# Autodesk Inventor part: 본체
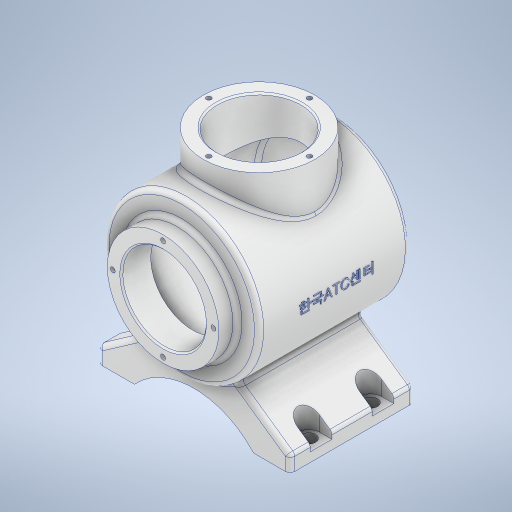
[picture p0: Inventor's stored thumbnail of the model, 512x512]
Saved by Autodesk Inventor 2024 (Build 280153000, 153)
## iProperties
Created: 2023-08
Part Number: 본체
Material: 알루미늄 6061
Document SubType Name: Modeling
Designer: Owner
Density: 2.7 g/cm^3
Appearance: 알루미늄 - 평지
Mass: 1315.98 g
Surface Area: 1059.75 cm^2
Volume: 487.401 cm^3
Author: Owner
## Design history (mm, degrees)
sketch "스케치1"
  geometry: L1 (0, 0)-(36, 0); L2 (36, 0)-(36, -12); L3 (36, -12)-(0, -12); L4 (0, -12)-(0, 0); L5 (0, -12)-(50, -12); L6 (50, -12)-(50, -120); L7 (50, -120)-(0, -120); L8 (0, -120)-(0, -12); A1 r 113 centre (0, -7) between (0, -120) and (50, -108.336); 2 further points
  constraints: 16 end point, 4 parallel, 2 horizontal, 2 perpendicular, 2 point on circle, 1 centre point, 1 midpoint, 1 point on line, 1 vertical alignment
  dimensions: "d6" = 72 diameter of L2 point (0, -6); "d7" = 100 diameter of L6 L8; "d8" = 12 distance of L1.end L2.end; "d9" = 108 distance of L5.end L6.end; "d10" = 113 radius of A1
revolve "회전1" sketch "스케치1" stored, may be unused: angle "d11" = 90 deg
sketch "스케치2"
  geometry: L1 (-50, -108.336)-(-50, -12) reference; L2 (-50, -12)-(-36, -12) reference; L3 (-36, -12)-(-36, 0) reference; L4 (-36, 0)-(36, 0) reference; L5 (36, 0)-(36, -12) reference; L6 (36, -12)-(50, -12) reference; L7 (50, -12)-(50, -108.336) reference; L8 (43, -103.887)-(43, -19); L9 (43, -19)-(27, -19); L10 (-29, 0)-(-29, -19); L11 (-29, -19)-(-43, -19); L12 (-43, -19)-(-43, -103.887); L13 (27, 0)-(-29, 0); L14 (0, 0)-(0, -113); L15 (50, -108.336)-(-50, -108.336) reference; L16 (27, 0)-(27, -19); A1 r 113 centre (0, -7) between (-50, -108.336) and (0, -120) reference; A2 r 113 centre (0, -7) between (0, -120) and (50, -108.336) reference; A3 r 106 centre (0, -7) between (-43, -103.887) and (0, -113); A4 r 106 centre (0, -7) between (0, -113) and (43, -103.887); 3 further points
  constraints: 16 end point, 4 point on circle, 2 centre point, 2 point on line, 1 collinear, 1 perpendicular, 1 vertical, 5 other
  dimensions: "d12" = 7 distance between parallel lines of L7 L8; "d13" = 7 radial gap between concentric circles of A1 A4; "d86" = 54 diameter of L16 L14
revolve "회전2" sketch "스케치2" stored, may be unused: angle "d14" = 360 deg
fillet "모깎기1" dims "d15" = 3
chamfer "모따기1" distance "d16" = 1; stored, may be unused: second distance "d17" = 2, angle "d18" = 45 deg
fillet "모깎기2" dims "d19" = 3
sketch "스케치3"
  geometry: A1 r 32.5 centre (0, 0) between (0, 32.5) and (32.5, 0); 3 further points
  constraints: 4 point on circle, 2 horizontal alignment, 2 vertical alignment, 1 centre point, 1 coincident
  dimensions: "d20" = 65 diameter of A1
hole "구멍1" sketch "스케치3" at (0, 32.5), (32.5, 0), (0, -32.5), (-32.5, 0) diameter "d21" = 3.242; stored, may be unused: countersink angle "d25" = 90 deg, drill point angle "d27" = 118 deg; dims "d22" = 8, "d23" = 4, "d24" = 2, "d26" = 10
node "작업 평면1"
sketch "스케치4"
  geometry: C1 r 36 at (0, -62); 1 further point
  constraints: 1 centre point, 1 vertical alignment
  dimensions: "d29" = 72 diameter of C1; "d30" = 62 distance of point (0, 0) C1.centre
extrude "돌출1" join sketch "스케치4" stored distance "d31" = 10; taper "d32" = 0 deg
sketch "스케치5"
  geometry: C1 r 36 at (0, 0) reference; C2 r 27 at (0, 0); 1 further point
  constraints: 1 centre point, 1 coincident
  dimensions: "d33" = 54 diameter of C2
extrude "돌출2" cut sketch "스케치5" stored distance "d34" = 10; taper "d35" = 0 deg
chamfer "모따기2" distance "d36" = 1; stored, may be unused: second distance "d37" = 2, angle "d38" = 45 deg
sketch "스케치6"
  geometry: C1 r 36 at (0, 0) reference; C2 r 28 at (0, 0) reference; A1 r 32.5 centre (0, 0) between (-32.5, 0) and (0, 32.5); 4 further points
  constraints: 4 point on circle, 2 horizontal alignment, 2 vertical alignment, 1 centre point, 1 coincident
  dimensions: "d39" = 65 diameter of A1
hole "구멍2" sketch "스케치6" at (-32.5, 0), (0, 32.5), (32.5, 0), (0, -32.5) diameter "d40" = 3.242; stored, may be unused: countersink angle "d44" = 90 deg, drill point angle "d46" = 118 deg; dims "d41" = 8, "d42" = 4, "d43" = 2, "d45" = 10
node "작업 평면2"
node "작업 평면3"
sketch "스케치9"
  geometry: L1 (-26.694, -42.278)-(-62, -67); L2 (-62, -67)-(-62, -77); L3 (-62, -77)-(-38.5, -77); L4 (38.5, -77)-(62, -77); L5 (62, -77)-(62, -67); L6 (62, -67)-(26.694, -42.278); A1 r 50 centre (0, 0) between (-26.694, -42.278) and (26.694, -42.278) reference; A2 r 52.096 centre (0, -112.096) between (38.5, -77) and (-38.5, -77); 5 further points
  constraints: 12 end point, 5 point on circle, 3 equal length, 3 midpoint, 2 perpendicular, 1 centre point, 1 horizontal, 1 horizontal alignment, 1 vertical
  dimensions: "d57" = 55 deg angle of L1 L2; "d58" = 55 deg angle of L5 L6; "d59" = 10 distance of L1.end L2.end; "d60" = 77 distance from line of L4 point (0, 0); "d61" = 77 distance of L4.start L3.end; "d62" = 17 vertical distance of point (50.25, -77) point (0, -60); "d63" = 124 distance of point (62, -72) point (-62, -72)
extrude "돌출4" join sketch "스케치9" distance "d64" = 80; taper "d65" = 0 deg
node "작업 평면4"
sketch "스케치10"
  geometry: L1 (23.5, 0)-(23.5, -80) reference; L2 (23.5, -80)-(-6.483, -80) reference; L3 (-6.483, -80)-(-6.483, 0) reference; L4 (-6.483, 0)-(23.5, 0) reference; L5 (-100.5, -80)-(-100.5, 0) reference; L6 (-100.5, 0)-(-70.517, 0) reference; L7 (-70.517, 0)-(-70.517, -80) reference; L8 (-70.517, -80)-(-100.5, -80) reference; L9 (23.5, -13)-(15.5, -13); L10 (15.5, -13)-(15.5, -27); L11 (15.5, -27)-(23.5, -27); L12 (23.5, -27)-(23.5, -13); L13 (23.5, -53)-(15.5, -53); L14 (15.5, -53)-(15.5, -67); L15 (15.5, -67)-(23.5, -67); L16 (23.5, -67)-(23.5, -53); A1 r 7 centre (15.5, -20) between (15.5, -13) and (15.5, -27); A2 r 7 centre (15.5, -60) between (15.5, -53) and (15.5, -67); 3 further points
  constraints: 16 end point, 4 parallel, 4 point on circle, 4 tangent, 3 point on line, 2 centre point, 2 horizontal, 2 midpoint, 2 perpendicular
  dimensions: "d67" = 14 distance of L11.end L9.start; "d68" = 14 distance of L13.end L14.end; "d70" = 20 distance from line of L4 point (15.5, -20); "d71" = 40 distance of point (15.5, -20) point (15.5, -60); "d72" = 8 distance of L10.end L11.end
extrude "돌출5" cut sketch "스케치10" distance "d73" = 30; taper "d74" = 0 deg
sketch "스케치11"
  geometry: L1 (-6.483, -80)-(-6.483, 0) reference; L2 (-6.483, 0)-(23.5, 0) reference; L3 (23.5, 0)-(23.5, -13) reference; L4 (23.5, -13)-(23.5, -27) reference; L5 (15.5, -27)-(23.5, -27) reference; L6 (23.5, -13)-(15.5, -13) reference; L7 (23.5, -80)-(-6.483, -80) reference; L8 (23.5, -67)-(23.5, -80) reference; L9 (15.5, -67)-(23.5, -67) reference; L10 (23.5, -53)-(15.5, -53) reference; L11 (23.5, -53)-(23.5, -67) reference; L12 (23.5, -27)-(23.5, -53) reference; L13 (-100.5, -80)-(-100.5, 0) reference; L14 (-100.5, 0)-(-70.517, 0) reference; L15 (-70.517, 0)-(-70.517, -80) reference; L16 (-70.517, -80)-(-100.5, -80) reference; C1 r 4.5 at (15.5, -20); C2 r 4.5 at (15.5, -60); A1 r 7 centre (15.5, -20) between (15.5, -13) and (15.5, -27) reference; A2 r 7 centre (15.5, -60) between (15.5, -53) and (15.5, -67) reference; 1 further point
  constraints: 2 centre point, 2 coincident
  dimensions: "d75" = 9 diameter of C1; "d76" = 9 diameter of C2
extrude "돌출6" cut sketch "스케치11" distance "d77" = 30; taper "d78" = 0 deg
fillet "모깎기3" dims "d79" = 3
fillet "모깎기4" dims "d80" = 3
fillet "모깎기5" dims "d81" = 3
node "작업 평면5"
sketch "스케치12"
  geometry: 2 further points
  constraints: 1 vertical alignment, 1 other
  dimensions: "d82" = 62 distance of point (0, 60.168) point (0, -1.832)
feature "엠보싱1" sketch "스케치12" dims "d6" = 72, "d7" = 100, "d8" = 12, "d9" = 108, "d10" = 113, "d12" = 7, "d13" = 7, "d83" = 0.5, "d84" = 0, "d86" = 54
fillet "모깎기6" dims "d85" = 3
node "솔리드1"
mirror "미러1"
node "절단 모서리 투영1"
node "절단 모서리 투영2"
node "절단 모서리 투영3"
node "절단 모서리 투영5"
node "절단 모서리 투영6"
feature "A9D066F2-1C7D-4E18-AEED-F7BC21143FA4" dims "d21" = 3.242, "d22" = 8, "d23" = 4, "d24" = 2, "d25" = 90 deg, "d26" = 10, "d27" = 118 deg
other parameters: "d28" = 65, "d47" = -77, "d66" = -6
